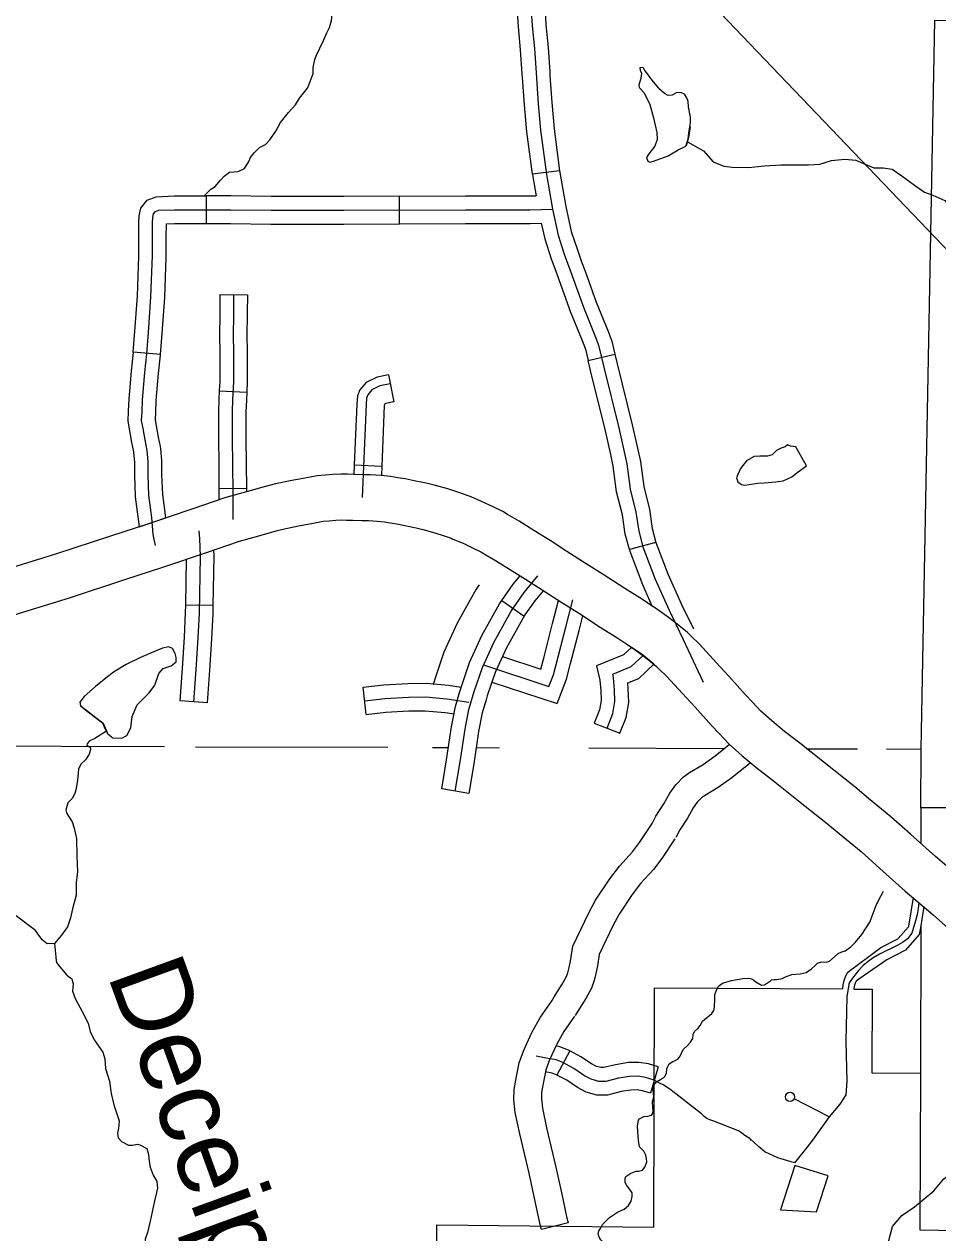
# Model space of a CAD drawing. Extents: x 813775 to 1157140, y 1757555 to 1979907.
# Drawn here: x 965544 to 975520, y 1838441 to 1851635 of the extents above; entities that cross this region are included whole.
import ezdxf

# ---------------------------------------------------------------- set-up
doc = ezdxf.new("R2010")
doc.units = 0
for name, color, linetype in [('Level 10', 7, 'Continuous'), ('Level 31', 7, 'Continuous'), ('Level 32', 7, 'Continuous'), ('Level 33', 7, 'Continuous'), ('Level 34', 7, 'Continuous'), ('Level 35', 7, 'Continuous'), ('Level 46', 7, 'Continuous'), ('Level 5', 7, 'Continuous'), ('Level 6', 7, 'Continuous'), ('R_Draft', 7, 'Continuous')]:
    doc.layers.add(name, color=color, linetype=linetype)

msp = doc.modelspace()

# ---------------------------------------------------------------- linework, layer by layer
at = {"layer": 'Level 10'}
for points in [[(969143, 1846720), (969073, 1846721), (969001, 1846723), (968915, 1846718), (968834, 1846712), (968742, 1846704), (968591, 1846676), (968465, 1846653), (968290, 1846618), (968165, 1846585), (967970, 1846531), (967746, 1846467), (967608, 1846420), (967375, 1846341), (966900, 1846182), (966487, 1846047), (965888, 1845849), (965212, 1845643), (965004, 1845586), (964875, 1845548)], [(972412, 1845276), (972297, 1845353), (972102, 1845473), (971865, 1845629), (971681, 1845743), (971470, 1845879), (971286, 1845998), (971108, 1846109), (970948, 1846209), (970822, 1846283), (970770, 1846314), (970666, 1846366), (970537, 1846426), (970423, 1846474), (970392, 1846487), (970291, 1846523), (970170, 1846563), (970037, 1846599), (969934, 1846624), (969802, 1846651), (969704, 1846671), (969625, 1846684), (969545, 1846698), (969442, 1846707), (969327, 1846716), (969239, 1846717), (969146, 1846720)], [(965014, 1845068), (965140, 1845105), (965351, 1845163), (966040, 1845372), (966643, 1845572), (967057, 1845707), (967534, 1845867), (967769, 1845947), (967895, 1845990), (968106, 1846050), (968295, 1846103), (968402, 1846130), (968559, 1846162), (968682, 1846185), (968810, 1846208), (968874, 1846214), (968947, 1846219), (969009, 1846223), (969063, 1846222), (969134, 1846220)], [(969131, 1846220), (969227, 1846217), (969303, 1846216), (969400, 1846209), (969480, 1846201), (969542, 1846191), (969613, 1846179), (969701, 1846161), (969824, 1846136), (969913, 1846114), (970027, 1846084), (970130, 1846050), (970207, 1846023), (970225, 1846014), (970336, 1845968), (970448, 1845916), (970530, 1845875), (970568, 1845853), (970689, 1845782), (970844, 1845684), (971019, 1845576), (971199, 1845459), (971413, 1845321), (971596, 1845208), (971833, 1845051), (972027, 1844932), (972134, 1844861)], [(975721, 1842356), (975493, 1842550), (975221, 1842793), (975008, 1842981), (974763, 1843184), (974613, 1843309), (974385, 1843490), (974014, 1843786), (973845, 1843913), (973709, 1844030), (973588, 1844136), (973495, 1844233), (973419, 1844315), (973239, 1844519), (973139, 1844622), (972917, 1844866), (972827, 1844953), (972787, 1844993), (972675, 1845086), (972581, 1845159), (972499, 1845217), (972415, 1845274)], [(972131, 1844863), (972214, 1844806), (972285, 1844756), (972361, 1844697), (972450, 1844623), (972478, 1844595), (972558, 1844517), (972775, 1844281), (972871, 1844180), (973049, 1843979), (973131, 1843891), (973241, 1843775), (973381, 1843652), (973532, 1843523), (973708, 1843391), (974073, 1843099), (974297, 1842921), (974443, 1842799), (974683, 1842602), (974888, 1842419), (975164, 1842172), (975398, 1841974)], [(975393, 1841979), (975472, 1841909), (975665, 1841738), (975831, 1841602), (975987, 1841476), (976139, 1841370), (976222, 1841316), (976302, 1841261), (976365, 1841224), (976406, 1841198)]]:
    msp.add_lwpolyline(points, dxfattribs=at)
at = {"layer": 'Level 31'}
for p, q in [((971391, 1850034), (971094, 1849996)), ((967531, 1849760), (967531, 1849460)), ((969644, 1849456), (969642, 1849756)), ((967033, 1848030), (966734, 1848056)), ((966734, 1848056), (966734, 1848056)), ((971702, 1847963), (971994, 1848034)), ((971994, 1848034), (971994, 1848034)), ((972442, 1845975), (972152, 1845899)), ((970758, 1845342), (971004, 1845171)), ((970298, 1844341), (970298, 1844341)), ((971769, 1844005), (972048, 1843894)), ((970399, 1843237), (970103, 1843287))]:
    msp.add_line(p, q, dxfattribs=at)
for points in [[(970928, 1853021), (970961, 1852807), (971006, 1852490), (971030, 1852332), (971059, 1852134), (971079, 1851878), (971081, 1851777), (971090, 1851617), (971115, 1851369), (971133, 1851104), (971157, 1850767)], [(970986, 1851054), (970983, 1851094), (970965, 1851356), (970941, 1851605), (970931, 1851771), (970929, 1851870), (970911, 1852106)], [(971210, 1852130), (971229, 1851885), (971231, 1851783), (971240, 1851628), (971264, 1851381), (971282, 1851115), (971285, 1851076)], [(971094, 1849996), (971034, 1850461), (971008, 1850755), (970986, 1851054)], [(971285, 1851076), (971307, 1850780), (971332, 1850493), (971391, 1850034)], [(971157, 1850767), (971183, 1850477), (971246, 1849993), (971311, 1849616)], [(971094, 1849996), (971097, 1849970), (971133, 1849760)], [(971391, 1850034), (971394, 1850015), (971458, 1849644), (971517, 1849371), (971584, 1849173), (971631, 1849041)], [(966795, 1849102), (966795, 1849111), (966795, 1849313), (966797, 1849467), (966800, 1849542), (966819, 1849628), (966886, 1849715), (966984, 1849752), (967181, 1849760), (967435, 1849760), (967531, 1849760)], [(968587, 1849753), (968242, 1849753), (967800, 1849760), (967531, 1849760)], [(969642, 1849756), (969033, 1849753), (968587, 1849753)], [(969642, 1849756), (970362, 1849760), (970699, 1849760)], [(970699, 1849760), (971133, 1849760)], [(966903, 1848270), (966929, 1848657), (966945, 1849108), (966945, 1849311), (966947, 1849463), (966949, 1849523), (966958, 1849564)], [(966958, 1849564), (966978, 1849590), (967014, 1849603), (967184, 1849610), (967435, 1849610), (967799, 1849610), (968240, 1849603)], [(968240, 1849603), (969033, 1849603), (970362, 1849610), (971067, 1849610), (971311, 1849616)], [(971311, 1849616), (971373, 1849331), (971442, 1849124), (971526, 1848887), (971651, 1848546), (971776, 1848237), (971816, 1848130), (971874, 1847891), (972037, 1847228)], [(967094, 1849092), (967095, 1849106), (967095, 1849310), (967097, 1849456), (967186, 1849460), (967435, 1849460), (967531, 1849460)], [(967531, 1849460), (967798, 1849460), (968239, 1849453), (968587, 1849453)], [(968587, 1849453), (969034, 1849453), (969644, 1849456)], [(969644, 1849456), (970363, 1849460), (970699, 1849460)], [(970699, 1849460), (971069, 1849460), (971190, 1849463)], [(971190, 1849463), (971228, 1849291), (971300, 1849075), (971348, 1848940)], [(966734, 1848056), (966753, 1848282), (966780, 1848665), (966795, 1849102)], [(967033, 1848030), (967052, 1848259), (967079, 1848650), (967094, 1849092)], [(971631, 1849041), (971668, 1848938), (971791, 1848599), (971916, 1848292), (971960, 1848174), (971994, 1848034)], [(971348, 1848940), (971385, 1848836), (971511, 1848492), (971636, 1848183), (971673, 1848086), (971702, 1847963)], [(966978, 1845945), (966954, 1846063), (966938, 1846248), (966907, 1846489), (966898, 1846715), (966898, 1846861), (966887, 1846981), (966865, 1847097), (966842, 1847222), (966827, 1847309), (966831, 1847404), (966836, 1847535), (966862, 1847834), (966883, 1848036), (966903, 1848270)], [(966734, 1848056), (966733, 1848050), (966713, 1847848), (966686, 1847544), (966681, 1847410), (966676, 1847300), (966695, 1847196), (966717, 1847070), (966737, 1846966)], [(967032, 1847023), (967012, 1847125), (966990, 1847249), (966977, 1847319), (966981, 1847398), (966985, 1847526), (967012, 1847820), (967032, 1848022), (967033, 1848030)], [(971948, 1846939), (971891, 1847194), (971729, 1847856), (971702, 1847963)], [(971994, 1848034), (972020, 1847927), (972183, 1847263), (972241, 1847005)], [(972037, 1847228), (972125, 1846836), (972161, 1846559), (972223, 1846309), (972255, 1846099), (972299, 1845929), (972433, 1845577), (972585, 1845237), (972741, 1844918), (972957, 1844452)], [(966737, 1846966), (966738, 1846960), (966748, 1846854), (966748, 1846712), (966757, 1846477), (966800, 1846149)], [(966800, 1846149), (967090, 1846246), (967057, 1846502), (967048, 1846718), (967048, 1846868), (967036, 1847002), (967032, 1847023)], [(972152, 1845899), (972108, 1846069), (972076, 1846280), (972013, 1846531), (971977, 1846809), (971948, 1846939)], [(972241, 1847005), (972273, 1846862), (972309, 1846587), (972371, 1846338), (972402, 1846129), (972442, 1845975)], [(972442, 1845975), (972572, 1845634), (972721, 1845301), (972851, 1845034)], [(972152, 1845899), (972156, 1845884), (972294, 1845519), (972399, 1845285)], [(970251, 1843262), (970305, 1843582), (970359, 1843938), (970400, 1844152), (970457, 1844349), (970547, 1844611), (970676, 1844894), (970861, 1845227), (971002, 1845431), (971152, 1845612)], [(970758, 1845342), (970883, 1845522), (970958, 1845613)], [(970512, 1845514), (970478, 1845466), (970273, 1845097), (970128, 1844778), (970027, 1844484), (970010, 1844423)], [(971004, 1845171), (971122, 1845340), (971213, 1845450)], [(970298, 1844341), (970314, 1844394), (970407, 1844667), (970541, 1844962), (970733, 1845307), (970758, 1845342)], [(970558, 1844641), (971274, 1844405), (971323, 1844532), (971459, 1845054), (971535, 1845351)], [(971220, 1844730), (971314, 1845092), (971378, 1845343)], [(971004, 1845171), (970988, 1845148), (970810, 1844827), (970686, 1844556), (970600, 1844304), (970587, 1844259)], [(971510, 1844655), (971604, 1845017), (971645, 1845175)], [(972419, 1844648), (972290, 1844753), (972176, 1844832), (972089, 1844750), (971794, 1844629), (971831, 1844475), (971841, 1844362), (971844, 1844251), (971827, 1844149), (971769, 1844005)], [(970651, 1844453), (971363, 1844218), (971466, 1844486), (971510, 1844655)], [(970766, 1844731), (971184, 1844593), (971220, 1844730)], [(971909, 1843949), (971972, 1844109), (971994, 1844241), (971990, 1844370), (971980, 1844499), (971970, 1844539), (972172, 1844622), (972305, 1844747)], [(972048, 1843894), (972118, 1844068), (972145, 1844231), (972140, 1844379), (972135, 1844445), (972254, 1844494), (972419, 1844648)], [(970103, 1843287), (970157, 1843606), (970211, 1843964), (970255, 1844187), (970298, 1844341)], [(970587, 1844259), (970546, 1844117), (970506, 1843912), (970453, 1843559), (970399, 1843237)]]:
    msp.add_lwpolyline(points, dxfattribs=at)
at = {"layer": 'Level 32'}
for p, q in [((967681, 1848683), (967981, 1848679)), ((969521, 1847807), (969581, 1847513)), ((967674, 1847632), (967974, 1847618)), ((969148, 1846824), (969448, 1846811)), ((967670, 1846568), (967970, 1846570)), ((967608, 1845289), (967308, 1845294)), ((969280, 1844100), (969246, 1844398)), ((967547, 1844227), (967248, 1844248)), ((971503, 1840427), (971361, 1840163)), ((972468, 1840253), (972381, 1839966))]:
    msp.add_line(p, q, dxfattribs=at)
for points in [[(967681, 1848683), (967679, 1848491), (967677, 1848208), (967680, 1848085), (967679, 1847736), (967674, 1847632)], [(967831, 1848681), (967829, 1848490), (967827, 1848209), (967830, 1848086), (967829, 1847733), (967820, 1847534), (967816, 1847406), (967815, 1847116), (967819, 1846826), (967821, 1846519), (967821, 1846229)], [(967981, 1848679), (967979, 1848489), (967977, 1848210), (967980, 1848087), (967979, 1847729), (967974, 1847618)], [(969521, 1847807), (969397, 1847781), (969277, 1847723), (969211, 1847643), (969183, 1847577), (969177, 1847488), (969148, 1846824)], [(969541, 1847709), (969429, 1847686), (969340, 1847643), (969297, 1847590), (969281, 1847553), (969277, 1847483), (969233, 1846467)], [(967674, 1847632), (967670, 1847539), (967666, 1847408), (967665, 1847115), (967669, 1846824), (967670, 1846568)], [(967974, 1847618), (967970, 1847529), (967966, 1847404), (967965, 1847117), (967969, 1846827), (967970, 1846570)], [(969581, 1847513), (969494, 1847495), (969477, 1847487), (969476, 1847472), (969448, 1846811)], [(969148, 1846824), (969144, 1846720)], [(969448, 1846811), (969444, 1846707)], [(967670, 1846568), (967671, 1846518), (967671, 1846442)], [(967970, 1846570), (967971, 1846531)], [(967398, 1844237), (967423, 1844592), (967443, 1844935), (967457, 1845206), (967468, 1845825), (967461, 1846019), (967455, 1846104)], [(967608, 1845289), (967618, 1845827), (967616, 1845895)], [(967308, 1845294), (967318, 1845794)], [(967248, 1844248), (967273, 1844602), (967293, 1844943), (967307, 1845212), (967308, 1845294)], [(967547, 1844227), (967572, 1844582), (967593, 1844926), (967607, 1845201), (967608, 1845289)], [(969246, 1844398), (969468, 1844423), (969735, 1844439), (969934, 1844441), (970177, 1844418), (970315, 1844397)], [(969263, 1844249), (969481, 1844273), (969740, 1844289), (969927, 1844291), (970159, 1844269), (970400, 1844233)], [(969280, 1844100), (969494, 1844124), (969745, 1844139), (969921, 1844141), (970141, 1844120), (970238, 1844105)], [(971503, 1840427), (971489, 1840435), (971394, 1840473), (971350, 1840481)], [(972424, 1840109), (972328, 1840138), (972246, 1840152), (972155, 1840149), (972032, 1840129), (971894, 1840094), (971818, 1840094), (971735, 1840118), (971662, 1840156), (971546, 1840234), (971425, 1840299), (971352, 1840328), (971245, 1840348), (971135, 1840369)], [(972468, 1840253), (972362, 1840285), (972256, 1840302), (972141, 1840299), (972001, 1840276), (971875, 1840244), (971840, 1840244), (971792, 1840258), (971738, 1840285), (971623, 1840363), (971503, 1840427)], [(971362, 1840163), (971310, 1840183), (971232, 1840198)], [(972381, 1839966), (972295, 1839992), (972236, 1840001), (972169, 1840000), (972063, 1839982), (971913, 1839944), (971796, 1839944), (971679, 1839978), (971585, 1840027), (971468, 1840106), (971361, 1840163)]]:
    msp.add_lwpolyline(points, dxfattribs=at)
at = {"layer": 'Level 33'}
for points in [[(975314, 1842046), (975306, 1841980), (975293, 1841916), (975275, 1841846), (975235, 1841714), (975223, 1841695), (975202, 1841667), (975189, 1841652), (975169, 1841634), (975133, 1841610), (975084, 1841582), (974883, 1841482), (974815, 1841443), (974759, 1841402), (974706, 1841358), (974655, 1841306), (974599, 1841236), (974552, 1841171), (974548, 1841164)], [(974552, 1841171), (974525, 1841022), (974516, 1840528), (974525, 1840096), (974516, 1839949), (974449, 1839846), (974333, 1839708), (974151, 1839454), (974088, 1839374)], [(974333, 1839708), (973950, 1839902)]]:
    msp.add_lwpolyline(points, dxfattribs=at)
msp.add_circle((973906, 1839925), 50, dxfattribs=at)
at = {"layer": 'Level 34'}
for points in [[(973485, 1839450), (973467, 1839470), (973425, 1839498), (973398, 1839515), (973376, 1839533), (973345, 1839553), (973075, 1839659), (973030, 1839676), (972998, 1839690), (972970, 1839712), (972939, 1839739), (972593, 1840011), (972522, 1840056), (972481, 1840076), (972424, 1840109)], [(974088, 1839374), (973955, 1839205), (973772, 1839258), (973630, 1839325), (973563, 1839383), (973467, 1839470)]]:
    msp.add_lwpolyline(points, dxfattribs=at)
at = {"layer": 'Level 35'}
for points in [[(968226, 1850374), (968293, 1850467), (968342, 1850560), (968432, 1850671), (968508, 1850756), (968551, 1850829), (968636, 1850938), (968655, 1850979), (968698, 1851098), (968698, 1851161), (968717, 1851248), (968731, 1851291), (968812, 1851457), (968850, 1851542), (968878, 1851599), (968899, 1851675), (968907, 1851740)], [(972312, 1850886), (972263, 1850941), (972260, 1850978), (972282, 1851044), (972287, 1851095), (972274, 1851129), (972271, 1851161), (972300, 1851164), (972321, 1851124), (972412, 1851007), (972471, 1850936)], [(972312, 1850886), (972374, 1850757), (972414, 1850611), (972451, 1850454), (972454, 1850375), (972430, 1850305), (972364, 1850218), (972340, 1850178), (972353, 1850138), (972377, 1850127), (972417, 1850141)], [(972818, 1850619), (972797, 1850731), (972794, 1850792), (972781, 1850832), (972754, 1850872), (972722, 1850885), (972672, 1850888), (972619, 1850861), (972576, 1850858), (972534, 1850877), (972481, 1850927), (972471, 1850936)], [(972417, 1850141), (972574, 1850199), (972685, 1850263), (972770, 1850303), (972794, 1850380), (972802, 1850446), (972818, 1850561), (972818, 1850619)], [(972815, 1850515), (972797, 1850399), (972772, 1850308)], [(967508, 1849760), (967582, 1849833), (967628, 1849863), (967688, 1849931), (967729, 1849977), (967786, 1850018), (967881, 1850026), (967949, 1850061), (967998, 1850137), (968017, 1850181), (968057, 1850230), (968114, 1850290), (968180, 1850320), (968226, 1850374)], [(972785, 1850352), (972963, 1850251), (973066, 1850134), (973183, 1850084), (973276, 1850073), (973454, 1850070), (973627, 1850089), (973805, 1850100), (974108, 1850100), (974230, 1850108), (974360, 1850148), (974503, 1850161)], [(974503, 1850161), (974625, 1850149), (974710, 1850114), (974821, 1850066), (974922, 1850066), (975021, 1850053), (975127, 1849979), (975265, 1849878), (975376, 1849800), (975467, 1849769), (975597, 1849710), (975634, 1849667), (975677, 1849617), (975698, 1849569)], [(973411, 1846604), (973556, 1846623), (973624, 1846629), (973750, 1846638), (973830, 1846649), (973927, 1846695), (973996, 1846749), (974087, 1846815), (973970, 1847021), (973910, 1847030), (973879, 1847044), (973853, 1847021), (973810, 1847007), (973759, 1846981), (973710, 1846935), (973659, 1846918), (973576, 1846918), (973513, 1846915), (973430, 1846867), (973367, 1846784), (973336, 1846718), (973321, 1846684), (973336, 1846638), (973378, 1846609), (973411, 1846604)], [(966322, 1844404), (966199, 1844294), (966151, 1844234), (966159, 1844194), (966245, 1844125), (966399, 1844008), (966425, 1843945), (966459, 1843888), (966514, 1843845), (966611, 1843842), (966665, 1843871), (966708, 1843954), (966722, 1844079), (966779, 1844205), (966908, 1844337), (966971, 1844420), (967014, 1844546), (967062, 1844600), (967148, 1844629), (967205, 1844674), (967203, 1844720), (967194, 1844766), (967163, 1844818), (967122, 1844838), (967054, 1844823), (966942, 1844775), (966814, 1844723), (966659, 1844646), (966519, 1844563), (966436, 1844497), (966322, 1844404)], [(966166, 1844189), (966405, 1844006), (966451, 1843901)], [(966442, 1843916), (966316, 1843839), (966253, 1843807), (966231, 1843779), (966228, 1843765), (966265, 1843742), (966268, 1843716), (966253, 1843667), (966213, 1843604), (966162, 1843556), (966139, 1843501), (966125, 1843381), (966113, 1843292), (966099, 1843238), (966068, 1843184), (966022, 1843135), (965999, 1843055), (966011, 1843018), (966068, 1842929), (966091, 1842858), (966116, 1842746), (966119, 1842557)], [(965876, 1841600), (965794, 1841595), (965739, 1841641), (965668, 1841741), (965462, 1841898), (965333, 1842015), (965325, 1842055), (965333, 1842124), (965333, 1842190), (965293, 1842261), (965245, 1842327), (964990, 1842450), (964759, 1842522), (964553, 1842567)], [(966119, 1842557), (966125, 1842382), (966113, 1842270), (966111, 1842127), (966071, 1841978), (966051, 1841881), (966016, 1841781), (965953, 1841689), (965876, 1841600)], [(974336, 1841406), (974433, 1841490), (974471, 1841509), (974508, 1841520), (974569, 1841564), (974620, 1841614), (974692, 1841696), (974779, 1841833), (974851, 1842026), (974900, 1842123), (974926, 1842172)], [(965876, 1841600), (965886, 1841490), (965894, 1841411), (965897, 1841392), (965935, 1841343), (966011, 1841254), (966065, 1841213), (966079, 1841158), (966073, 1841080), (966101, 1840998), (966177, 1840857), (966242, 1840729), (966264, 1840639), (966307, 1840549), (966402, 1840413), (966424, 1840342), (966432, 1840236), (966476, 1840097), (966495, 1839961), (966525, 1839838), (966552, 1839751), (966582, 1839664), (966576, 1839585), (966565, 1839528), (966571, 1839479), (966606, 1839439), (966685, 1839398), (966728, 1839398), (966783, 1839409), (966807, 1839400), (966883, 1839360), (966902, 1839297), (966910, 1839218)], [(973083, 1840906), (973087, 1840992), (973086, 1841041), (973106, 1841099), (973124, 1841134), (973168, 1841168), (973269, 1841194), (973391, 1841218), (973457, 1841220), (973495, 1841211), (973533, 1841181), (973596, 1841146), (973628, 1841150), (973692, 1841192), (973704, 1841203), (973734, 1841207), (973758, 1841205), (973823, 1841218), (973856, 1841235), (973925, 1841260), (974018, 1841270), (974082, 1841282), (974139, 1841322), (974181, 1841358), (974208, 1841383), (974249, 1841399), (974300, 1841396), (974336, 1841406)], [(972707, 1840368), (972738, 1840442), (972784, 1840484), (972819, 1840524), (972846, 1840562), (972850, 1840605), (972864, 1840639), (972901, 1840672), (972924, 1840706), (972950, 1840752), (972993, 1840788), (973029, 1840816), (973052, 1840835), (973075, 1840867), (973083, 1840906)], [(972416, 1839958), (972413, 1840025), (972419, 1840053), (972450, 1840088), (972493, 1840114), (972537, 1840144), (972556, 1840183), (972561, 1840231), (972572, 1840257), (972586, 1840284), (972628, 1840311), (972661, 1840325), (972685, 1840340), (972707, 1840368)], [(972311, 1839331), (972264, 1839379), (972250, 1839452), (972245, 1839547), (972242, 1839608), (972250, 1839670), (972262, 1839685), (972309, 1839710), (972352, 1839713), (972394, 1839724), (972409, 1839746), (972412, 1839773), (972408, 1839812), (972404, 1839870), (972419, 1839924), (972416, 1839958), (972412, 1840006)], [(974955, 1838246), (975026, 1838510), (975127, 1838630), (975265, 1838725), (975477, 1838899), (975586, 1839030), (975686, 1839109), (975863, 1839345), (975961, 1839495)], [(971935, 1838610), (972024, 1838667), (972097, 1838699), (972142, 1838739), (972172, 1838786), (972184, 1838838), (972181, 1838878), (972151, 1838924), (972123, 1838958), (972106, 1838992), (972105, 1839034), (972115, 1839056), (972158, 1839086), (972188, 1839098), (972227, 1839113), (972253, 1839114), (972294, 1839126), (972320, 1839156), (972336, 1839193), (972343, 1839215), (972340, 1839254), (972332, 1839289), (972311, 1839331)], [(966910, 1839218), (966919, 1839158), (966954, 1839071), (966992, 1839001), (967000, 1838930), (966965, 1838772), (966919, 1838568), (966891, 1838443), (966864, 1838372), (966870, 1838310), (966924, 1838217), (966949, 1838133), (967025, 1838016), (967122, 1837904), (967209, 1837828)], [(972007, 1838192), (971996, 1838237), (971961, 1838285), (971904, 1838323), (971878, 1838333), (971840, 1838363), (971824, 1838393), (971813, 1838429), (971820, 1838461), (971837, 1838490), (971858, 1838531), (971897, 1838573), (971935, 1838610)]]:
    msp.add_lwpolyline(points, dxfattribs=at)
at = {"layer": 'Level 46'}
for points in [[(972393, 1842895), (972442, 1842990), (972529, 1843125), (972595, 1843239), (972659, 1843332), (972743, 1843419), (972810, 1843465), (972958, 1843554), (973090, 1843648), (973243, 1843773)], [(973473, 1843573), (973272, 1843409), (973123, 1843303), (972972, 1843213), (972938, 1843189), (972892, 1843142), (972849, 1843079), (972785, 1842968), (972702, 1842839), (972658, 1842756)], [(971302, 1840967), (971332, 1841019), (971418, 1841154), (971466, 1841238), (971481, 1841280), (971494, 1841336), (971509, 1841408), (971534, 1841570), (971709, 1841935), (971783, 1842074), (971939, 1842307), (972044, 1842445), (972185, 1842599), (972263, 1842702), (972401, 1842909)], [(972650, 1842742), (972507, 1842528), (972416, 1842407), (972275, 1842253), (972184, 1842133), (972041, 1841919), (971977, 1841799), (971823, 1841480), (971804, 1841356), (971787, 1841272), (971769, 1841195), (971740, 1841113), (971676, 1840999), (971588, 1840862), (971560, 1840815)], [(971192, 1838477), (971178, 1838532), (971119, 1838800), (971057, 1839091), (970955, 1839521), (970906, 1839756), (970891, 1839891), (970893, 1840006), (970918, 1840147), (970950, 1840298), (970995, 1840425), (971034, 1840509), (971092, 1840635), (971181, 1840796), (971308, 1840977)], [(971554, 1840805), (971436, 1840637), (971360, 1840499), (971306, 1840384), (971274, 1840312), (971239, 1840216), (971213, 1840090), (971193, 1839977), (971191, 1839904), (971203, 1839803), (971247, 1839587), (971350, 1839158), (971413, 1838864), (971470, 1838601), (971483, 1838549), (971192, 1838477)]]:
    msp.add_lwpolyline(points, dxfattribs=at)
at = {"layer": 'Level 5'}
for points in [[(964820, 1843757), (967077, 1843749)], [(967416, 1843748), (969515, 1843741)], [(970001, 1843739), (970177, 1843739)], [(970480, 1843738), (970734, 1843737)], [(971711, 1843734), (973184, 1843729)], [(974088, 1843726), (974642, 1843724)], [(974960, 1843723), (975338, 1843722)], [(975336, 1843082), (975335, 1842690)], [(975333, 1841794), (975329, 1840185)]]:
    msp.add_lwpolyline(points, dxfattribs=at)
at = {"layer": 'Level 6'}
for points in [[(977930, 1841190), (977931, 1841665), (976821, 1842091), (975682, 1843081), (975336, 1843082), (975338, 1843722), (975487, 1851679), (978086, 1851659), (978037, 1849008), (980636, 1848989), (980685, 1851640), (983283, 1851620), (983332, 1854270), (985208, 1854255)], [(972669, 1833232), (970031, 1833244), (970051, 1838527), (972418, 1838502), (972426, 1841117), (974483, 1841103), (974484, 1841108), (974488, 1841150), (974497, 1841196), (974516, 1841245), (974537, 1841286), (974899, 1841555), (975082, 1841649), (975087, 1841653), (975199, 1841781), (975204, 1841789), (975254, 1842100)], [(975366, 1842005), (975329, 1841771), (975316, 1841696), (975168, 1841525), (974964, 1841421), (974657, 1841211), (974629, 1841187), (974619, 1841165), (974611, 1841146), (974608, 1841130), (974604, 1841107), (974603, 1841102), (974803, 1841101), (974801, 1840188), (975329, 1840185), (975325, 1838472), (976560, 1838452)]]:
    msp.add_lwpolyline(points, dxfattribs=at)
msp.add_lwpolyline([(974196, 1838671), (974324, 1839064), (973960, 1839176), (973803, 1838693)], close=True, dxfattribs=at)
msp.add_lwpolyline([(974196, 1838671), (974324, 1839064), (973960, 1839176), (973803, 1838693)], close=True, dxfattribs=at)
msp.add_lwpolyline([(974196, 1838671), (974324, 1839064), (973960, 1839176), (973803, 1838693)], close=True, dxfattribs=at)
at = {"layer": 'R_Draft'}
msp.add_line((982982, 1841465), (928075, 1898928), dxfattribs=at)

# ---------------------------------------------------------------- texts
at = {"layer": 'Level 35'}
msp.add_text('Deceiper', height=844.8, rotation=290.0004, dxfattribs=at).set_placement((966449, 1841259))

doc.saveas('drawing.dxf')
